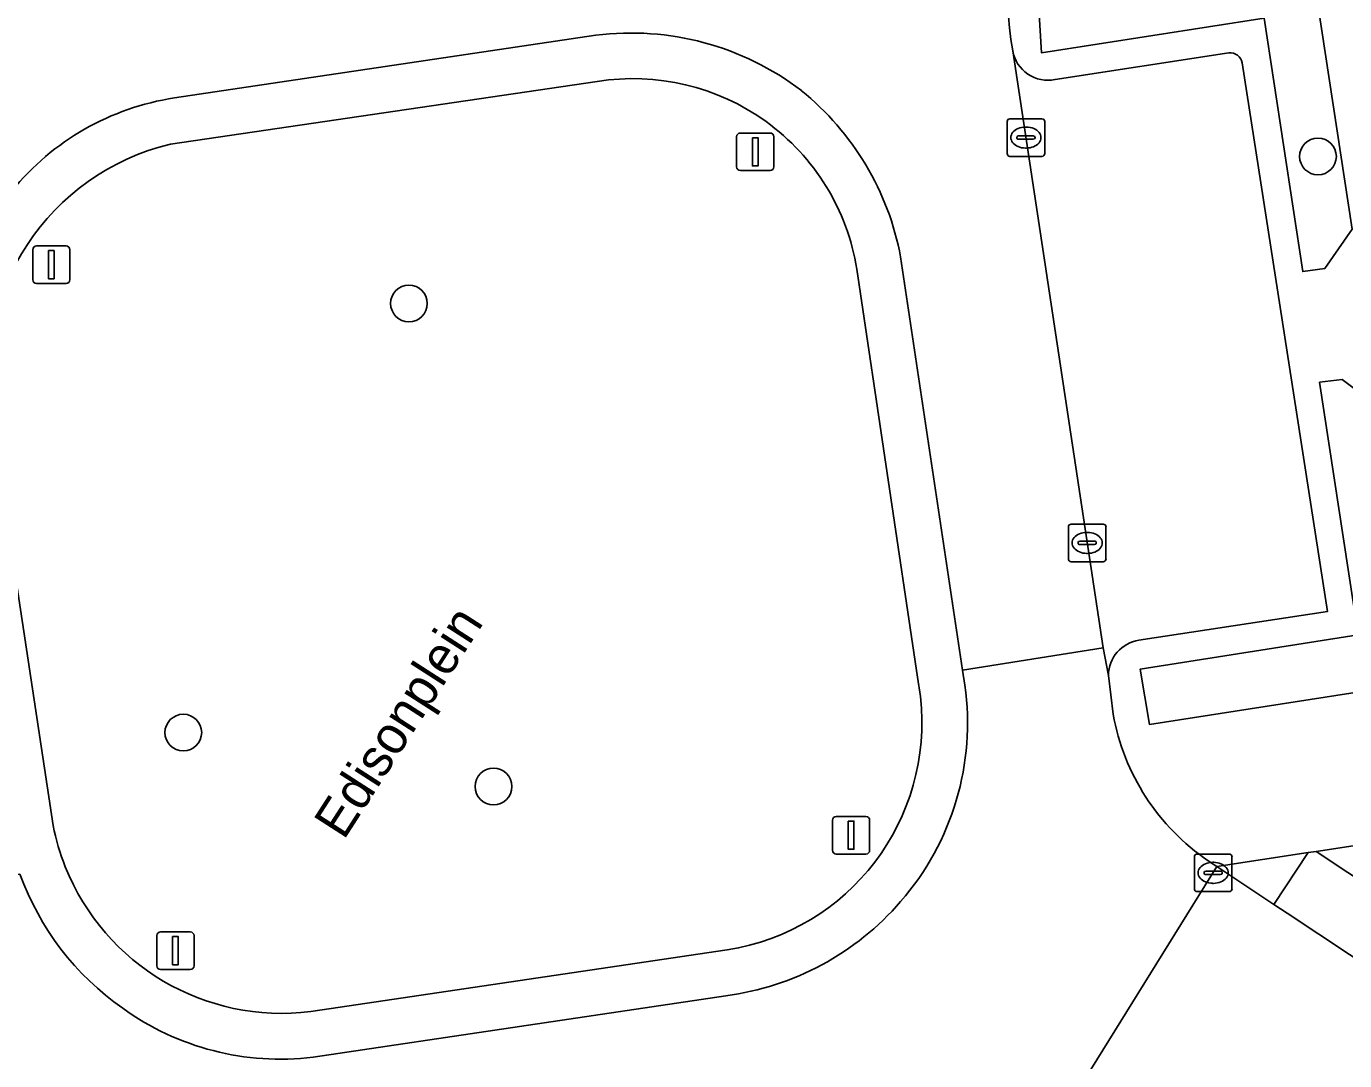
# Model space of a CAD drawing. Extents: x 159279 to 160377, y 384531 to 385888.
# Drawn here: x 159893.98 to 159929.07, y 384932.85 to 384960.39 of the extents above; entities that cross this region are included whole.
import ezdxf

# ---------------------------------------------------------------- set-up
doc = ezdxf.new("R2010")
doc.units = 0
for name, color, linetype in [('IMGEO_Boom', 7, 'Continuous'), ('IMGEO_Groenvoorziening', 7, 'Continuous'), ('IMGEO_Haag', 7, 'Continuous'), ('IMGEO_Kolk', 7, 'Continuous'), ('IMGEO_Lichtmast', 7, 'Continuous'), ('IMGEO_Openbare_ruimte_label', 7, 'Continuous'), ('IMGEO_Parkeervlak_open', 7, 'Continuous'), ('IMGEO_Rijbaan_lokaal_open', 7, 'Continuous'), ('IMGEO_Voetpad_open', 7, 'Continuous')]:
    doc.layers.add(name, color=color, linetype=linetype)

msp = doc.modelspace()

# ---------------------------------------------------------------- linework, layer by layer
at = {"layer": 'IMGEO_Boom'}
for centre in [(159928.357, 384956.93), (159904.16, 384953.015), (159898.154, 384941.588), (159906.411, 384940.153)]:
    msp.add_circle(centre, 0.489, dxfattribs=at)
at = {"layer": 'IMGEO_Groenvoorziening'}
for points in [[(159928.538, 384953.947), (159929.264, 384954.992), (159928.255, 384961.623), (159927.525, 384962.204), (159920.911, 384961.171), (159920.999, 384959.687), (159926.928, 384960.609), (159927.952, 384953.865)], [(159930.432, 384942.827), (159930.984, 384943.589), (159930.004, 384950.233), (159929.001, 384950.987), (159928.399, 384950.919), (159929.431, 384944.191), (159923.625, 384943.279), (159923.872, 384941.805)]]:
    msp.add_lwpolyline(points, close=True, dxfattribs=at)
for points in [[(159909.173, 384958.925), (159897.812, 384957.26)], [(159917.775, 384942.549), (159917.699, 384943.061), (159916.084, 384953.925)], [(159893.031, 384950.034), (159894.688, 384939.118)], [(159901.547, 384934.163), (159912.631, 384935.802)]]:
    msp.add_lwpolyline(points, dxfattribs=at)
for centre, radius, start, end in [((159910.132, 384952.975), 6.027, 9.0706, 99.1591), ((159899.313, 384951.072), 6.367, 103.633, 189.3867), ((159911.684, 384941.858), 6.13, 278.8864, 6.4689), ((159900.802, 384940.32), 6.231, 191.1238, 201.7116), ((159900.77, 384940.313), 6.199, 201.7581, 277.2005)]:
    msp.add_arc(centre, radius, start, end, dxfattribs=at)
at = {"layer": 'IMGEO_Haag'}
for points in [[(159928.538, 384953.947), (159929.264, 384954.992), (159928.255, 384961.623), (159927.525, 384962.204), (159920.911, 384961.171), (159920.999, 384959.687), (159926.928, 384960.609), (159927.952, 384953.865)], [(159930.432, 384942.827), (159930.984, 384943.589), (159930.004, 384950.233), (159929.001, 384950.987), (159928.399, 384950.919), (159929.431, 384944.191), (159923.625, 384943.279), (159923.872, 384941.805)]]:
    msp.add_lwpolyline(points, close=True, dxfattribs=at)
at = {"layer": 'IMGEO_Kolk'}
for p, q in [((159920.157, 384957.932), (159921.009, 384957.932)), ((159920.082, 384957.006), (159920.082, 384957.858)), ((159920.57, 384957.712), (159920.595, 384957.712)), ((159921.083, 384957.858), (159921.083, 384957.006)), ((159920.341, 384957.426), (159920.341, 384957.438)), ((159920.779, 384957.389), (159920.381, 384957.389)), ((159920.384, 384957.475), (159920.782, 384957.475)), ((159920.825, 384957.438), (159920.825, 384957.426)), ((159921.009, 384956.932), (159920.157, 384956.932)), ((159920.593, 384957.152), (159920.568, 384957.152)), ((159921.713, 384946.214), (159921.713, 384947.066)), ((159921.788, 384947.14), (159922.64, 384947.14)), ((159922.714, 384947.066), (159922.714, 384946.214)), ((159921.972, 384946.634), (159921.972, 384946.646)), ((159922.015, 384946.683), (159922.413, 384946.683)), ((159922.201, 384946.92), (159922.226, 384946.92)), ((159922.456, 384946.646), (159922.456, 384946.634)), ((159922.41, 384946.597), (159922.012, 384946.597)), ((159922.224, 384946.36), (159922.199, 384946.36)), ((159922.64, 384946.14), (159921.788, 384946.14)), ((159925.067, 384937.429), (159925.067, 384938.281)), ((159925.142, 384938.355), (159925.994, 384938.355)), ((159926.068, 384938.281), (159926.068, 384937.429)), ((159925.326, 384937.849), (159925.326, 384937.861)), ((159925.369, 384937.898), (159925.767, 384937.898)), ((159925.555, 384938.135), (159925.58, 384938.135)), ((159925.81, 384937.861), (159925.81, 384937.849)), ((159925.764, 384937.812), (159925.366, 384937.812)), ((159925.578, 384937.575), (159925.553, 384937.575)), ((159925.994, 384937.355), (159925.142, 384937.355))]:
    msp.add_line(p, q, dxfattribs=at)
for points in [[(159920.157, 384957.932), (159921.009, 384957.932)], [(159920.082, 384957.006), (159920.082, 384957.858)], [(159921.083, 384957.858), (159921.083, 384957.006)], [(159921.009, 384956.932), (159920.157, 384956.932)], [(159921.713, 384946.214), (159921.713, 384947.066)], [(159921.788, 384947.14), (159922.64, 384947.14)], [(159922.714, 384947.066), (159922.714, 384946.214)], [(159922.64, 384946.14), (159921.788, 384946.14)], [(159925.067, 384937.429), (159925.067, 384938.281)], [(159925.142, 384938.355), (159925.994, 384938.355)], [(159926.068, 384938.281), (159926.068, 384937.429)], [(159925.994, 384937.355), (159925.142, 384937.355)]]:
    msp.add_lwpolyline(points, dxfattribs=at)
for centre, radius, start, end in [((159920.159, 384957.856), 0.0765, 91.552, 178.448), ((159920.159, 384957.856), 0.0765, 91.552, 178.448), ((159921.007, 384957.856), 0.0765, 1.552, 88.448), ((159921.007, 384957.856), 0.0765, 1.552, 88.448), ((159920.381, 384957.435), 0.0403, 85.8775, 175.7526), ((159920.378, 384957.425), 0.0366, 178.938, 274.7102), ((159920.782, 384957.432), 0.043, 264.8664, 352.4533), ((159920.786, 384957.437), 0.0386, 1.7309, 96.639), ((159920.159, 384957.008), 0.0765, 181.552, 268.448), ((159920.159, 384957.008), 0.0765, 181.552, 268.448), ((159921.007, 384957.008), 0.0765, 271.552, 358.448), ((159921.007, 384957.008), 0.0765, 271.552, 358.448), ((159921.79, 384947.064), 0.0765, 91.552, 178.448), ((159921.79, 384947.064), 0.0765, 91.552, 178.448), ((159922.638, 384947.064), 0.0765, 1.552, 88.448), ((159922.638, 384947.064), 0.0765, 1.552, 88.448), ((159922.012, 384946.643), 0.0403, 85.8775, 175.7526), ((159922.009, 384946.633), 0.0366, 178.938, 274.7102), ((159922.413, 384946.64), 0.043, 264.8664, 352.4533), ((159922.417, 384946.645), 0.0386, 1.7309, 96.639), ((159921.79, 384946.216), 0.0765, 181.552, 268.448), ((159921.79, 384946.216), 0.0765, 181.552, 268.448), ((159922.638, 384946.216), 0.0765, 271.552, 358.448), ((159922.638, 384946.216), 0.0765, 271.552, 358.448), ((159925.144, 384938.279), 0.0765, 91.552, 178.448), ((159925.144, 384938.279), 0.0765, 91.552, 178.448), ((159925.992, 384938.279), 0.0765, 1.552, 88.448), ((159925.992, 384938.279), 0.0765, 1.552, 88.448), ((159925.366, 384937.858), 0.0403, 85.8775, 175.7526), ((159925.771, 384937.86), 0.0386, 1.7309, 96.639), ((159925.363, 384937.848), 0.0366, 178.938, 274.7102), ((159925.767, 384937.855), 0.043, 264.8664, 352.4533), ((159925.144, 384937.431), 0.0765, 181.552, 268.448), ((159925.144, 384937.431), 0.0765, 181.552, 268.448), ((159925.992, 384937.431), 0.0765, 271.552, 358.448), ((159925.992, 384937.431), 0.0765, 271.552, 358.448)]:
    msp.add_arc(centre, radius, start, end, dxfattribs=at)
for centre, major_axis, ratio, start_param, end_param in [((159920.569, 384957.432), (-0.387, 0.002), 0.722429, 4.712389, 7.853982), ((159920.594, 384957.432), (-0.39, 0.002), 0.717154, 1.570796, 4.712389), ((159922.2, 384946.64), (-0.387, 0.002), 0.722429, 4.712389, 7.853982), ((159922.225, 384946.64), (-0.39, 0.002), 0.717154, 1.570796, 4.712389), ((159925.554, 384937.855), (-0.387, 0.002), 0.722429, 4.712389, 7.853982), ((159925.579, 384937.855), (-0.39, 0.002), 0.717154, 1.570796, 4.712389)]:
    msp.add_ellipse(centre, major_axis=major_axis, ratio=ratio, start_param=start_param, end_param=end_param, dxfattribs=at)
at = {"layer": 'IMGEO_Lichtmast'}
for p, q in [((159912.982, 384957.553), (159913.772, 384957.553)), ((159913.772, 384957.553), (159912.982, 384957.553)), ((159912.882, 384956.653), (159912.882, 384957.453)), ((159912.882, 384957.453), (159912.882, 384956.653)), ((159913.872, 384957.453), (159913.872, 384956.653)), ((159913.872, 384956.653), (159913.872, 384957.453)), ((159913.772, 384956.553), (159912.982, 384956.553)), ((159912.982, 384956.553), (159913.772, 384956.553)), ((159894.146, 384953.647), (159894.146, 384954.447)), ((159894.146, 384954.447), (159894.146, 384953.647)), ((159894.246, 384954.547), (159895.036, 384954.547)), ((159895.036, 384954.547), (159894.246, 384954.547)), ((159895.136, 384954.447), (159895.136, 384953.647)), ((159895.136, 384953.647), (159895.136, 384954.447)), ((159895.036, 384953.547), (159894.246, 384953.547)), ((159894.246, 384953.547), (159895.036, 384953.547)), ((159915.533, 384939.356), (159916.323, 384939.356)), ((159916.323, 384939.356), (159915.533, 384939.356)), ((159915.433, 384938.456), (159915.433, 384939.256)), ((159915.433, 384939.256), (159915.433, 384938.456)), ((159916.423, 384939.256), (159916.423, 384938.456)), ((159916.423, 384938.456), (159916.423, 384939.256)), ((159916.323, 384938.356), (159915.533, 384938.356)), ((159915.533, 384938.356), (159916.323, 384938.356)), ((159897.45, 384935.382), (159897.45, 384936.182)), ((159897.45, 384936.182), (159897.45, 384935.382)), ((159897.55, 384936.282), (159898.34, 384936.282)), ((159898.34, 384936.282), (159897.55, 384936.282)), ((159898.44, 384936.182), (159898.44, 384935.382)), ((159898.44, 384935.382), (159898.44, 384936.182)), ((159898.34, 384935.282), (159897.55, 384935.282)), ((159897.55, 384935.282), (159898.34, 384935.282))]:
    msp.add_line(p, q, dxfattribs=at)
for points in [[(159913.302, 384957.428), (159913.452, 384957.428), (159913.452, 384956.678), (159913.302, 384956.678), (159913.302, 384957.428)], [(159894.566, 384954.422), (159894.716, 384954.422), (159894.716, 384953.672), (159894.566, 384953.672), (159894.566, 384954.422)], [(159915.853, 384939.231), (159916.003, 384939.231), (159916.003, 384938.481), (159915.853, 384938.481), (159915.853, 384939.231)], [(159897.87, 384936.157), (159898.02, 384936.157), (159898.02, 384935.407), (159897.87, 384935.407), (159897.87, 384936.157)]]:
    msp.add_lwpolyline(points, dxfattribs=at)
for centre, start, end in [((159912.982, 384957.453), 90, 180), ((159912.982, 384957.453), 90, 180), ((159913.772, 384957.453), 0, 90), ((159913.772, 384957.453), 360, 90), ((159912.982, 384956.653), 180, 270), ((159912.982, 384956.653), 180, 270), ((159913.772, 384956.653), 270, 0), ((159913.772, 384956.653), 270, 0), ((159894.246, 384954.447), 90, 180), ((159894.246, 384954.447), 90, 180), ((159895.036, 384954.447), 0, 90), ((159895.036, 384954.447), 360, 90), ((159894.246, 384953.647), 180, 270), ((159894.246, 384953.647), 180, 270), ((159895.036, 384953.647), 270, 0), ((159895.036, 384953.647), 270, 0), ((159915.533, 384939.256), 90, 180), ((159915.533, 384939.256), 90, 180), ((159916.323, 384939.256), 0, 90), ((159916.323, 384939.256), 360, 90), ((159915.533, 384938.456), 180, 270), ((159915.533, 384938.456), 180, 270), ((159916.323, 384938.456), 270, 0), ((159916.323, 384938.456), 270, 0), ((159897.55, 384936.182), 90, 180), ((159897.55, 384936.182), 90, 180), ((159898.34, 384936.182), 0, 90), ((159898.34, 384936.182), 360, 90), ((159897.55, 384935.382), 180, 270), ((159897.55, 384935.382), 180, 270), ((159898.34, 384935.382), 270, 0), ((159898.34, 384935.382), 270, 0)]:
    msp.add_arc(centre, 0.1, start, end, dxfattribs=at)
at = {"layer": 'IMGEO_Parkeervlak_open'}
for points in [[(159920.235, 384959.739), (159922.636, 384943.844), (159922.778, 384943.112)], [(159925.985, 384959.687), (159921.357, 384958.979)], [(159923.592, 384944.048), (159928.606, 384944.812), (159926.337, 384959.421)]]:
    msp.add_lwpolyline(points, dxfattribs=at)
msp.add_lwpolyline([(159928.311, 384938.426), (159928.099, 384938.394), (159927.183, 384937.014), (159927.538, 384936.779), (159936.677, 384930.72), (159937.662, 384932.215)], close=True, dxfattribs=at)
for centre, radius, start, end in [((159921.163, 384959.902), 0.943, 189.9274, 281.8482), ((159926.015, 384959.361), 0.327, 10.5056, 95.339), ((159923.739, 384943.098), 0.961, 98.814, 179.1618)]:
    msp.add_arc(centre, radius, start, end, dxfattribs=at)
at = {"layer": 'IMGEO_Rijbaan_lokaal_open'}
for points in [[(159897.917, 384958.487), (159909.137, 384960.157)], [(159909.137, 384960.157), (159897.917, 384958.487)], [(159917.248, 384954.254), (159918.899, 384943.252), (159922.636, 384943.844), (159920.235, 384959.739)], [(159897.812, 384957.26), (159909.173, 384958.925)], [(159918.959, 384942.852), (159918.899, 384943.252), (159917.248, 384954.254)], [(159916.084, 384953.925), (159917.699, 384943.061), (159917.775, 384942.549)], [(159894.688, 384939.118), (159893.031, 384950.034)], [(159922.907, 384942.079), (159922.778, 384943.112), (159922.636, 384943.844), (159918.899, 384943.252), (159918.959, 384942.852)], [(159893.807, 384937.821), (159889.899, 384937.196), (159890.066, 384936.091), (159890.552, 384932.824), (159899.827, 384928.8), (159921.994, 384932.106), (159925.666, 384938.022), (159925.436, 384938.175)], [(159936.677, 384930.72), (159927.538, 384936.779), (159927.183, 384937.014), (159925.666, 384938.022), (159921.994, 384932.106)], [(159912.631, 384935.802), (159901.547, 384934.163)], [(159912.593, 384934.583), (159901.609, 384932.944)], [(159901.609, 384932.944), (159912.593, 384934.583)]]:
    msp.add_lwpolyline(points, dxfattribs=at)
for centre, radius, start, end in [((159926.43, 384960.973), 6.317, 146.6758, 191.2624), ((159910.073, 384952.741), 7.475, 52.6748, 97.1912), ((159910.073, 384952.741), 7.475, 52.6748, 97.1912), ((159910.132, 384952.975), 6.027, 9.0706, 99.1591), ((159909.919, 384952.886), 7.455, 10.5712, 51.0592), ((159909.919, 384952.886), 7.455, 10.5712, 51.0592), ((159898.953, 384951.658), 6.907, 98.6287, 140.8582), ((159898.953, 384951.658), 6.907, 98.6287, 140.8582), ((159899.313, 384951.072), 6.367, 103.633, 189.3867), ((159911.801, 384941.844), 7.228, 318.8841, 8.0151), ((159911.801, 384941.844), 7.228, 318.8841, 8.0151), ((159911.684, 384941.858), 6.13, 278.8864, 6.4689), ((159928.792, 384943.12), 5.976, 190.0327, 235.8374), ((159900.802, 384940.32), 6.231, 191.1238, 201.7116), ((159900.77, 384940.313), 6.199, 201.7581, 277.2005), ((159900.813, 384940.354), 7.45, 199.8808, 235.0109), ((159900.813, 384940.354), 7.45, 199.8808, 235.0109), ((159911.648, 384941.91), 7.387, 277.3532, 319.2865), ((159911.648, 384941.91), 7.387, 277.3532, 319.2865), ((159900.749, 384940.088), 7.196, 234.2139, 276.864), ((159900.749, 384940.088), 7.196, 234.2139, 276.864)]:
    msp.add_arc(centre, radius, start, end, dxfattribs=at)
at = {"layer": 'IMGEO_Voetpad_open'}
for points in [[(159925.436, 384938.175), (159925.666, 384938.022), (159928.099, 384938.394), (159928.311, 384938.426), (159934.331, 384939.346), (159933.907, 384942.703), (159933.789, 384943.295), (159932.965, 384948.873), (159932.16, 384954.319), (159931.355, 384959.765), (159930.173, 384967.765), (159934.703, 384974.467), (159937.871, 384979.153), (159938.432, 384979.992), (159951.23, 384999.12), (159950.682, 385000), (159921.539, 385046.778), (159920.97, 385047.69), (159895.629, 385088.366), (159894.998, 385089.378)], [(159921.357, 384958.979), (159925.985, 384959.687)], [(159926.337, 384959.421), (159928.606, 384944.812), (159923.592, 384944.048)], [(159922.778, 384943.112), (159922.907, 384942.079)], [(159934.331, 384939.346), (159928.311, 384938.426), (159937.662, 384932.215)]]:
    msp.add_lwpolyline(points, dxfattribs=at)
for points in [[(159927.525, 384962.204), (159928.255, 384961.623), (159929.264, 384954.992), (159928.538, 384953.947), (159927.952, 384953.865), (159926.928, 384960.609), (159920.999, 384959.687), (159920.911, 384961.171)], [(159928.399, 384950.919), (159929.001, 384950.987), (159930.004, 384950.233), (159930.984, 384943.589), (159930.432, 384942.827), (159923.872, 384941.805), (159923.625, 384943.279), (159929.431, 384944.191)], [(159928.099, 384938.394), (159925.666, 384938.022), (159927.183, 384937.014)]]:
    msp.add_lwpolyline(points, close=True, dxfattribs=at)
for centre, radius, start, end in [((159926.43, 384960.973), 6.317, 146.6758, 191.2624), ((159921.163, 384959.902), 0.943, 189.9274, 281.8482), ((159926.015, 384959.361), 0.327, 10.5056, 95.339), ((159923.739, 384943.098), 0.961, 98.814, 179.1618), ((159928.792, 384943.12), 5.976, 190.0327, 235.8374)]:
    msp.add_arc(centre, radius, start, end, dxfattribs=at)

# ---------------------------------------------------------------- texts
at = {"layer": 'IMGEO_Openbare_ruimte_label'}
msp.add_text('Edisonplein', height=1, rotation=57.2476, dxfattribs=at).set_placement((159902.425, 384938.704))

doc.saveas('drawing.dxf')
